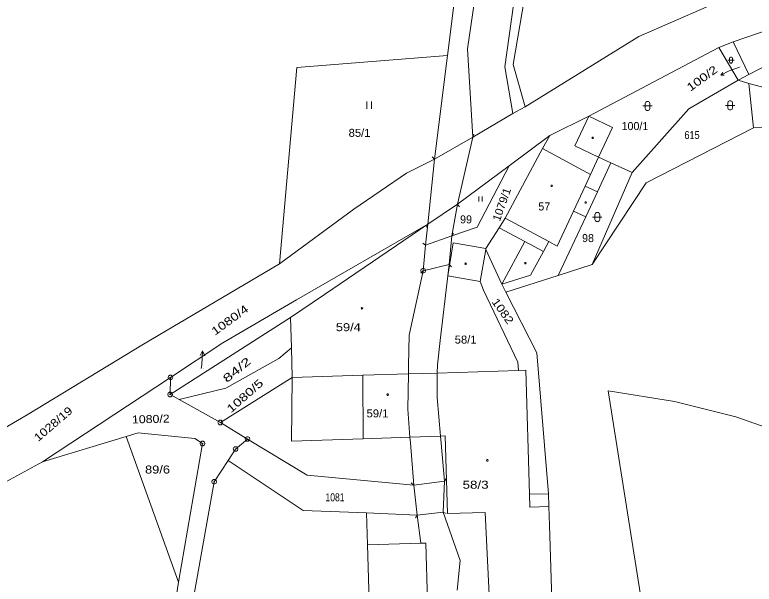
# Model space of a CAD drawing. Extents: x -687390 to -684106, y -954833 to -951648.
# Drawn here: x -687306.4 to -687149.2, y -952992 to -952870.9 of the extents above; entities that cross this region are included whole.
import ezdxf
from ezdxf.enums import TextEntityAlignment as Align

# ---------------------------------------------------------------- set-up
doc = ezdxf.new("R2010")
doc.units = 0
doc.header["$LTSCALE"] = 0.68
doc.header["$PDMODE"] = 32
doc.header["$PDSIZE"] = 0.34
for name, color, linetype, lineweight in [('1', 7, 'Continuous', 13), ('3', 7, 'Continuous', 13), ('4', 7, 'Continuous', 13), ('5', 7, 'Continuous', 13), ('7', 7, 'Continuous', 13), ('8', 7, 'Continuous', 13)]:
    doc.layers.add(name, color=color, linetype=linetype, lineweight=lineweight)
doc.layers.add('2', color=7, linetype='Continuous')

msp = doc.modelspace()

# ---------------------------------------------------------------- linework, layer by layer
at = {"layer": '1'}
for p, q in [((-687200.44, -952881.52), (-687194.11, -952844.49)), ((-687137.55, -952871.11), (-687153.68, -952876.68)), ((-687156.73, -952877.87), (-687153.68, -952876.68)), ((-687153.68, -952876.68), (-687150.35, -952883.63)), ((-687214.4, -952879.57), (-687246.39, -952882.15)), ((-687246.39, -952882.15), (-687250.13, -952923.9)), ((-687152.65, -952884.86), (-687150.35, -952883.63)), ((-687149.41, -952894.96), (-687150.36, -952885.59)), ((-687209.05, -952896.98), (-687200.5, -952891.91)), ((-687192.66, -952896.58), (-687184.41, -952892.52)), ((-687179.35, -952894.88), (-687184.41, -952892.52)), ((-687179.35, -952894.88), (-687182.29, -952901.2)), ((-687209.05, -952896.98), (-687212.3, -952911.24)), ((-687217.16, -952901.68), (-687223.14, -952904.65)), ((-687217.16, -952901.68), (-687218.61, -952915.48)), ((-687182.29, -952901.2), (-687179.69, -952902.41)), ((-687182.57, -952908.59), (-687179.69, -952902.41)), ((-687179.69, -952902.41), (-687175.19, -952904.51)), ((-687223.14, -952904.65), (-687234.31, -952912.26)), ((-687175.19, -952904.51), (-687183.68, -952924.06)), ((-687212.3, -952911.24), (-687213.5, -952917.98)), ((-687250.13, -952923.9), (-687234.31, -952912.26)), ((-687218.61, -952915.48), (-687246.52, -952931.53)), ((-687218.61, -952915.48), (-687240.56, -952930.39)), ((-687214.08, -952924.02), (-687213.5, -952917.98)), ((-687213.17, -952919.46), (-687214.35, -952926.44)), ((-687206.25, -952920.65), (-687213.17, -952919.46)), ((-687202.83, -952928.24), (-687206.29, -952920.82)), ((-687250.13, -952923.9), (-687279.02, -952940.97)), ((-687219.57, -952925.37), (-687222.58, -952939.05)), ((-687214.08, -952924.02), (-687214.35, -952926.44)), ((-687190.88, -952926.41), (-687183.68, -952924.06)), ((-687202.03, -952929.94), (-687190.88, -952926.41)), ((-687207.46, -952927.65), (-687206.78, -952929.48)), ((-687202.03, -952929.94), (-687202.83, -952928.24)), ((-687199.44, -952944.82), (-687206.78, -952929.48)), ((-687195.4, -952942.85), (-687202.03, -952929.94)), ((-687246.52, -952931.53), (-687262.12, -952940.71)), ((-687240.56, -952930.39), (-687247.74, -952935.32)), ((-687247.74, -952935.32), (-687273.33, -952951.69)), ((-687247.57, -952941.76), (-687247.74, -952935.32)), ((-687222.58, -952939.05), (-687222.68, -952945.5)), ((-687303.75, -952956.02), (-687279.02, -952940.97)), ((-687273.28, -952948.06), (-687262.12, -952940.71)), ((-687250.23, -952944), (-687247.57, -952941.76)), ((-687247.39, -952948.08), (-687247.57, -952941.76)), ((-687195.4, -952942.85), (-687192.94, -952972.8)), ((-687222.71, -952947.31), (-687222.68, -952945.5)), ((-687216.58, -952947.13), (-687216.56, -952945.4)), ((-687232.39, -952947.61), (-687222.71, -952947.31)), ((-687222.71, -952947.31), (-687222.83, -952954.78)), ((-687216.64, -952952.3), (-687216.58, -952947.13)), ((-687300.47, -952965.97), (-687273.28, -952948.06)), ((-687247.39, -952948.08), (-687262.67, -952957.65)), ((-687247.39, -952948.08), (-687232.39, -952947.61)), ((-687171.85, -953003.77), (-687180.3, -952950.89)), ((-687180.3, -952950.89), (-687166.2, -952953.19)), ((-687215.9, -952960.52), (-687216.64, -952952.3)), ((-687153.12, -952956.45), (-687166.2, -952953.19)), ((-687222.39, -952960.75), (-687222.83, -952954.78)), ((-687303.75, -952956.02), (-687312.76, -952961.23)), ((-687256.9, -952961.15), (-687262.67, -952957.65)), ((-687271.54, -952991.58), (-687282.71, -952960.64)), ((-687222.3, -952961.97), (-687222.39, -952960.75)), ((-687215.9, -952960.52), (-687215.77, -952962.05)), ((-687266.46, -952962.12), (-687271.54, -952991.58)), ((-687221.58, -952970.93), (-687222.3, -952961.97)), ((-687215.04, -952970.08), (-687215.77, -952962.05)), ((-687261.03, -952965.73), (-687245.06, -952976.37)), ((-687221.58, -952970.93), (-687244.24, -952968.84)), ((-687221.58, -952970.93), (-687220.82, -952977.31)), ((-687215.35, -952976.69), (-687215.04, -952970.08)), ((-687192.94, -952972.8), (-687196.97, -952972.89)), ((-687192.94, -952972.8), (-687192.85, -952975.53)), ((-687192.74, -952979.44), (-687192.85, -952975.53)), ((-687231.39, -952983.63), (-687231.64, -952976.88)), ((-687220.82, -952977.31), (-687220.1, -952983.33)), ((-687220.1, -952983.33), (-687218.99, -952983.29)), ((-687218.99, -952983.29), (-687218.44, -953004.04)), ((-687231.39, -952983.63), (-687230.83, -953004.38)), ((-687277.05, -953023.53), (-687271.54, -952991.58))]:
    msp.add_line(p, q, dxfattribs=at)
for points in [[(-687185.17, -952712.96), (-687189.67, -952746.47), (-687192.16, -952809.95), (-687202.25, -952882.05), (-687200.5, -952891.91), (-687197.93, -952890.51)], [(-687209.05, -952896.98), (-687210.14, -952878.21), (-687200.8, -952814.48), (-687201.84, -952793.85)], [(-687200.44, -952881.52), (-687197.93, -952890.51), (-687173.78, -952875.55), (-687137.96, -952859.88), (-687092.93, -952845.31), (-687074.87, -952831.87)], [(-687217.16, -952901.68), (-687214.4, -952879.57), (-687210.68, -952849.7)], [(-687150.35, -952883.63), (-687133.97, -952875.12), (-687126.14, -952871.07)], [(-687175.19, -952904.51), (-687163.13, -952890.95), (-687152.65, -952884.86), (-687156.73, -952877.87), (-687184.41, -952892.52)], [(-687152.65, -952884.86), (-687150.36, -952885.59), (-687125.62, -952892.05)], [(-687125.62, -952892.05), (-687125.46, -952894.83), (-687149.41, -952894.96), (-687172.21, -952906.71), (-687183.68, -952924.06)], [(-687212.3, -952911.24), (-687201.31, -952903.03), (-687192.66, -952896.58)], [(-687202.14, -952914.18), (-687194.19, -952899.41), (-687192.66, -952896.58)], [(-687213.5, -952917.98), (-687208.14, -952916.13), (-687201.31, -952903.03)], [(-687190.88, -952926.41), (-687185.04, -952913.88), (-687182.57, -952908.59)], [(-687202.14, -952914.18), (-687203.44, -952916.22), (-687206.25, -952920.65)], [(-687218.61, -952915.48), (-687219.07, -952919.95), (-687219.57, -952925.37)], [(-687206.25, -952920.65), (-687206.29, -952920.82), (-687207.46, -952927.65)], [(-687216.56, -952945.4), (-687215.95, -952940.17), (-687214.35, -952926.44)], [(-687271.41, -952952.76), (-687261.49, -952950.37), (-687250.23, -952944)], [(-687199.44, -952944.82), (-687199.33, -952946.6), (-687216.58, -952947.13)], [(-687196.97, -952972.89), (-687197.78, -952946.54), (-687199.33, -952946.6)], [(-687273.28, -952948.06), (-687273.33, -952951.69), (-687271.41, -952952.76), (-687262.67, -952957.65)], [(-687124.67, -952968.53), (-687141.06, -952960.72), (-687153.12, -952956.45)], [(-687300.47, -952965.97), (-687282.71, -952960.64), (-687280.11, -952959.86)], [(-687280.11, -952959.86), (-687268.07, -952961.04), (-687266.46, -952962.12)], [(-687259.43, -952963.28), (-687256.9, -952961.15), (-687244.24, -952968.84)], [(-687269.03, -952998.54), (-687263.99, -952970.24), (-687261.03, -952965.73), (-687259.43, -952963.28)], [(-687349.14, -952979.54), (-687344.7, -952987.53), (-687323.81, -952978.41), (-687312.21, -952972.35), (-687300.47, -952965.97)], [(-687220.82, -952977.31), (-687231.64, -952976.88), (-687245.06, -952976.37)], [(-687212.39, -952993.27), (-687211.72, -952986.95), (-687215.35, -952976.69)], [(-687191.97, -953005.64), (-687192.2, -952997.53), (-687192.74, -952979.44)]]:
    msp.add_lwpolyline(points, dxfattribs=at)
at = {"layer": '3'}
for p, q in [((-687231.57, -952889.41), (-687231.57, -952890.91)), ((-687230.57, -952890.91), (-687230.57, -952889.41)), ((-687207.735, -952909.615), (-687207.735, -952910.62)), ((-687207.065, -952910.62), (-687207.065, -952909.615))]:
    msp.add_line(p, q, dxfattribs=at)
for points in [[(-687154.85, -952880.59), (-687153.999, -952880.59), (-687153.51, -952880.59)], [(-687172.9, -952890.34), (-687171.63, -952890.34), (-687170.9, -952890.34)], [(-687155.36, -952890.21), (-687154.09, -952890.21), (-687153.36, -952890.21)], [(-687183.58, -952913.95), (-687182.31, -952913.95), (-687181.58, -952913.95)]]:
    msp.add_lwpolyline(points, dxfattribs=at)
for points in [[(-687154.515, -952880.255), (-687154.448, -952880.061), (-687154.28, -952879.94), (-687154.073, -952879.94), (-687153.905, -952880.061), (-687153.838, -952880.255), (-687153.838, -952880.925), (-687153.905, -952881.119), (-687154.073, -952881.24), (-687154.28, -952881.24), (-687154.448, -952881.119), (-687154.515, -952880.925)], [(-687154.86, -952889.71), (-687154.76, -952889.42), (-687154.51, -952889.24), (-687154.2, -952889.24), (-687153.95, -952889.42), (-687153.85, -952889.71), (-687153.85, -952890.71), (-687153.95, -952891), (-687154.2, -952891.18), (-687154.51, -952891.18), (-687154.76, -952891), (-687154.86, -952890.71)], [(-687172.4, -952889.84), (-687172.3, -952889.55), (-687172.05, -952889.37), (-687171.74, -952889.37), (-687171.49, -952889.55), (-687171.39, -952889.84), (-687171.39, -952890.84), (-687171.49, -952891.13), (-687171.74, -952891.31), (-687172.05, -952891.31), (-687172.3, -952891.13), (-687172.4, -952890.84)], [(-687183.08, -952913.45), (-687182.98, -952913.16), (-687182.73, -952912.98), (-687182.42, -952912.98), (-687182.17, -952913.16), (-687182.07, -952913.45), (-687182.07, -952914.45), (-687182.17, -952914.74), (-687182.42, -952914.92), (-687182.73, -952914.92), (-687182.98, -952914.74), (-687183.08, -952914.45)]]:
    msp.add_lwpolyline(points, close=True, dxfattribs=at)
for p in [(-687210.56, -952923.87), (-687232.58, -952933.35)]:
    msp.add_point(p, dxfattribs=at)
at = {"layer": '4'}
for p, q in [((-687187.36, -952898.84), (-687184.41, -952892.52)), ((-687217.16, -952901.68), (-687209.05, -952896.98)), ((-687209.05, -952896.98), (-687208.835, -952896.306)), ((-687194.19, -952899.41), (-687184.02, -952904.9)), ((-687187.36, -952898.84), (-687182.29, -952901.2)), ((-687217.16, -952901.68), (-687217.657, -952901.177)), ((-687182.57, -952908.59), (-687185.17, -952907.38)), ((-687212.3, -952911.24), (-687218.61, -952915.48)), ((-687212.3, -952911.24), (-687211.844, -952911.78)), ((-687185.04, -952913.88), (-687187.64, -952912.67)), ((-687202.14, -952914.18), (-687192.9, -952919.17)), ((-687218.61, -952915.48), (-687218.878, -952916.134)), ((-687213.5, -952917.98), (-687213.124, -952917.381)), ((-687197.96, -952919.17), (-687203.44, -952916.22)), ((-687213.5, -952917.98), (-687219.07, -952919.95)), ((-687219.07, -952919.95), (-687219.631, -952919.52)), ((-687194.04, -952921.29), (-687197.96, -952919.17)), ((-687191.12, -952920.13), (-687192.9, -952919.17)), ((-687219.57, -952925.37), (-687220.07, -952925.87)), ((-687214.08, -952924.02), (-687219.57, -952925.37)), ((-687214.08, -952924.02), (-687213.58, -952924.52)), ((-687207.46, -952927.65), (-687214.35, -952926.44)), ((-687222.71, -952947.31), (-687216.58, -952947.13)), ((-687247.39, -952948.08), (-687247.57, -952961.64)), ((-687232.31, -952961.1), (-687222.39, -952960.75)), ((-687222.39, -952960.75), (-687215.9, -952960.52)), ((-687221.58, -952970.93), (-687222.121, -952970.475)), ((-687215.04, -952970.08), (-687221.58, -952970.93)), ((-687215.04, -952970.08), (-687214.637, -952969.499)), ((-687215.35, -952976.69), (-687220.82, -952977.31)), ((-687215.35, -952976.69), (-687214.709, -952976.987)), ((-687220.82, -952977.31), (-687221.215, -952977.897)), ((-687231.39, -952983.63), (-687220.1, -952983.33))]:
    msp.add_line(p, q, dxfattribs=at)
for points in [[(-687182.29, -952901.2), (-687184.02, -952904.9), (-687185.17, -952907.38)], [(-687185.17, -952907.38), (-687187.64, -952912.67), (-687191.12, -952920.13)], [(-687197.96, -952919.17), (-687202.83, -952928.24), (-687196.75, -952926.31)], [(-687192.9, -952919.17), (-687194.04, -952921.29), (-687196.75, -952926.31)], [(-687232.39, -952947.61), (-687232.31, -952961.1), (-687247.57, -952961.64)], [(-687215.9, -952960.52), (-687214.88, -952960.48), (-687214.4, -952977), (-687206.4, -952976.76), (-687204.98, -953005.92), (-687206.34, -953005.99), (-687206.22, -953008.27), (-687198.6, -953007.86)], [(-687196.97, -952972.89), (-687196.88, -952975.67), (-687192.85, -952975.53)]]:
    msp.add_lwpolyline(points, dxfattribs=at)
at = {"layer": '5'}
for points in [[(-687183.5, -952896.95), (-687183.41, -952897.1), (-687183.5, -952897.25), (-687183.68, -952897.25), (-687183.77, -952897.1), (-687183.68, -952896.95)], [(-687192.2, -952907.16), (-687192.11, -952907.31), (-687192.2, -952907.46), (-687192.38, -952907.46), (-687192.47, -952907.31), (-687192.38, -952907.16)], [(-687184.96, -952910.7), (-687184.87, -952910.85), (-687184.96, -952911), (-687185.14, -952911), (-687185.23, -952910.85), (-687185.14, -952910.7)], [(-687197.81, -952923.61), (-687197.72, -952923.76), (-687197.81, -952923.91), (-687197.99, -952923.91), (-687198.08, -952923.76), (-687197.99, -952923.61)], [(-687227.06, -952951.57), (-687226.97, -952951.72), (-687227.06, -952951.87), (-687227.24, -952951.87), (-687227.33, -952951.72), (-687227.24, -952951.57)], [(-687205.86, -952965.53), (-687205.77, -952965.68), (-687205.86, -952965.83), (-687206.04, -952965.83), (-687206.13, -952965.68), (-687206.04, -952965.53)]]:
    msp.add_lwpolyline(points, close=True, dxfattribs=at)
at = {"layer": '7'}
for p, q in [((-687156.355, -952883.813), (-687154.58, -952882.87)), ((-687152.35, -952882.07), (-687154.58, -952882.87)), ((-687266.44, -952942.414), (-687266.59, -952945.41)), ((-687266.73, -952946.15), (-687266.59, -952945.41))]:
    msp.add_line(p, q, dxfattribs=at)
for points in [[(-687155.606, -952883.794), (-687156.355, -952883.813), (-687155.921, -952883.203)], [(-687266.989, -952943.387), (-687266.44, -952942.414), (-687265.99, -952943.438)]]:
    msp.add_lwpolyline(points, dxfattribs=at)
at = {"layer": '8'}
for p, q in [((-687219.69, -952925.37), (-687219.45, -952925.37)), ((-687273.4, -952948.06), (-687273.16, -952948.06)), ((-687273.45, -952951.69), (-687273.21, -952951.69)), ((-687262.79, -952957.65), (-687262.55, -952957.65)), ((-687257.02, -952961.15), (-687256.78, -952961.15)), ((-687266.58, -952962.12), (-687266.34, -952962.12)), ((-687259.55, -952963.28), (-687259.31, -952963.28)), ((-687264.11, -952970.24), (-687263.87, -952970.24))]:
    msp.add_line(p, q, dxfattribs=at)
for points in [[(-687219.42, -952924.89), (-687219.17, -952925.07), (-687219.07, -952925.36), (-687219.17, -952925.65), (-687219.42, -952925.83), (-687219.73, -952925.83), (-687219.98, -952925.65), (-687220.08, -952925.36), (-687219.98, -952925.07), (-687219.73, -952924.89)], [(-687273.13, -952947.58), (-687272.88, -952947.76), (-687272.78, -952948.05), (-687272.88, -952948.34), (-687273.13, -952948.52), (-687273.44, -952948.52), (-687273.69, -952948.34), (-687273.79, -952948.05), (-687273.69, -952947.76), (-687273.44, -952947.58)], [(-687273.18, -952951.21), (-687272.93, -952951.39), (-687272.83, -952951.68), (-687272.93, -952951.97), (-687273.18, -952952.15), (-687273.49, -952952.15), (-687273.74, -952951.97), (-687273.84, -952951.68), (-687273.74, -952951.39), (-687273.49, -952951.21)], [(-687262.52, -952957.17), (-687262.27, -952957.35), (-687262.17, -952957.64), (-687262.27, -952957.93), (-687262.52, -952958.11), (-687262.83, -952958.11), (-687263.08, -952957.93), (-687263.18, -952957.64), (-687263.08, -952957.35), (-687262.83, -952957.17)], [(-687256.75, -952960.67), (-687256.5, -952960.85), (-687256.4, -952961.14), (-687256.5, -952961.43), (-687256.75, -952961.61), (-687257.06, -952961.61), (-687257.31, -952961.43), (-687257.41, -952961.14), (-687257.31, -952960.85), (-687257.06, -952960.67)], [(-687266.31, -952961.64), (-687266.06, -952961.82), (-687265.96, -952962.11), (-687266.06, -952962.4), (-687266.31, -952962.58), (-687266.62, -952962.58), (-687266.87, -952962.4), (-687266.97, -952962.11), (-687266.87, -952961.82), (-687266.62, -952961.64)], [(-687259.28, -952962.8), (-687259.03, -952962.98), (-687258.93, -952963.27), (-687259.03, -952963.56), (-687259.28, -952963.74), (-687259.59, -952963.74), (-687259.84, -952963.56), (-687259.94, -952963.27), (-687259.84, -952962.98), (-687259.59, -952962.8)], [(-687263.84, -952969.76), (-687263.59, -952969.94), (-687263.49, -952970.23), (-687263.59, -952970.52), (-687263.84, -952970.7), (-687264.15, -952970.7), (-687264.4, -952970.52), (-687264.5, -952970.23), (-687264.4, -952969.94), (-687264.15, -952969.76)]]:
    msp.add_lwpolyline(points, close=True, dxfattribs=at)

# ---------------------------------------------------------------- texts
at = {"layer": '2'}
for s, height, width, p in [('100/2', 0.1, 1.1, (-687152.304, -952882.07)), ('85/1', 1.7, 1.05, (-687235.425, -952896.9)), ('615', 1.7, 0.85, (-687164.056, -952897.37)), ('59/4', 1.7, 1.2, (-687238.135, -952938.22)), ('58/1', 1.7, 1.05, (-687212.875, -952940.86)), ('1080/4', 0.1, 1.1, (-687266.684, -952946.15)), ('59/1', 1.7, 1.05, (-687231.605, -952956.55)), ('89/6', 1.7, 1.2, (-687278.685, -952968.49)), ('58/3', 1.7, 1.25, (-687211.205, -952971.72)), ('1081', 1.7, 0.8, (-687240.335, -952974.4))]:
    msp.add_text(s, height=height, dxfattribs=dict(at, width=width)).set_placement(p)
for s, p in [('100/1', (-687177.425, -952895.46)), ('57', (-687195.105, -952912.55)), ('99', (-687211.735, -952915.3)), ('98', (-687185.815, -952919.28))]:
    msp.add_text(s, height=1.7, dxfattribs=at).set_placement(p)
for s, rotation, width, p in [('1079/1', 70.703, 1.05, (-687203.29, -952914.999)), ('1082', 305.387, 1.2, (-687205.115, -952931.98)), ('84/2', 39.362, 1.55, (-687261.293, -952949.269)), ('1080/5', 41.31, 1.35, (-687260.42, -952955.712)), ('1028/19', 40.565, 1.2, (-687301.393, -952961.809)), ('1080/2', 1.547, 1.15, (-687281.425, -952957.859))]:
    msp.add_text(s, height=1.7, rotation=rotation, dxfattribs=dict(at, width=width)).set_placement(p)
at = {"layer": '7', "width": 1.3}
msp.add_text('100/2', height=1.7, rotation=36.096, dxfattribs=at).set_placement((-687156.831, -952882.973), align=Align.RIGHT)
msp.add_text('1080/4', height=1.7, rotation=36.154, dxfattribs=at).set_placement((-687263.816, -952939.207))

doc.saveas('drawing.dxf')
